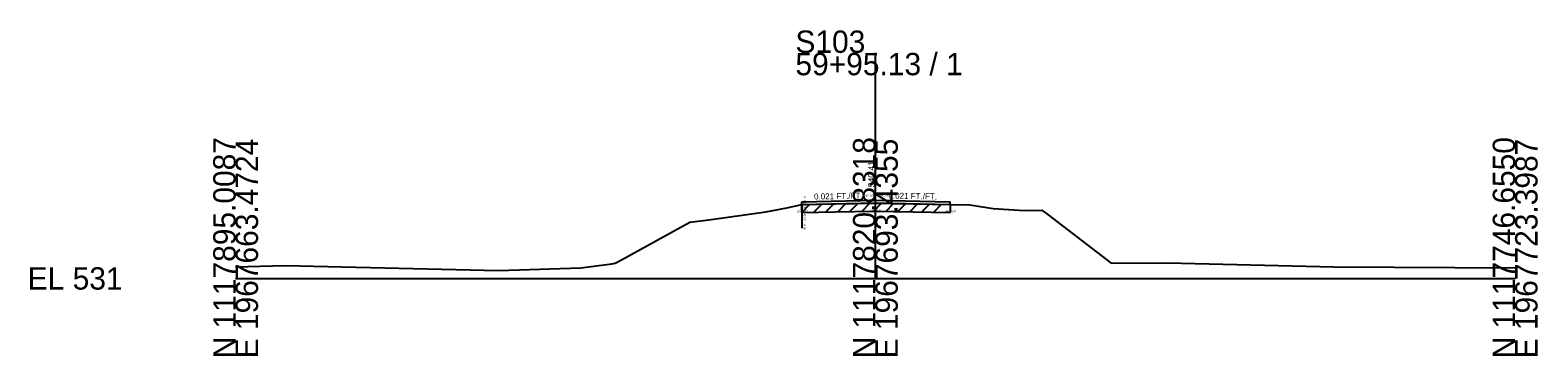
# Model space of a CAD drawing. Extents: x -26 to 163, y -10 to 24018.
# Drawn here: x -25.7 to 162.8, y 9490.3 to 9531.1 of the extents above; entities that cross this region are included whole.
import ezdxf

# ---------------------------------------------------------------- set-up
doc = ezdxf.new("R2010")
doc.units = 0
for name, color, linetype in [('RD_GPK_XS_Cell', 7, 'Continuous'), ('RD_XS_ExGround', 7, 'Continuous'), ('RD_XS_ExPaveRet', 7, 'Continuous'), ('RD_XS_Misc_Line', 7, 'Continuous'), ('RD_XS_PaveOvlay_CP', 7, 'Continuous'), ('RD_XS_TX_Elev_EX', 7, 'Continuous'), ('RD_XS_TX_ExEOP', 7, 'Continuous'), ('RD_XS_TX_Notes', 7, 'Continuous'), ('RD_XS_TX_Profile', 7, 'Continuous'), ('RD_XS_TX_Slope', 7, 'Continuous')]:
    doc.layers.add(name, color=color, linetype=linetype)

msp = doc.modelspace()

# ---------------------------------------------------------------- linework, layer by layer
at = {"layer": 'RD_GPK_XS_Cell'}
for p, q in [((80, 9500), (80, 9528.23)), ((0, 9500), (80, 9500)), ((80, 9500), (160, 9500))]:
    msp.add_line(p, q, dxfattribs=at)
at = {"layer": 'RD_XS_ExGround'}
msp.add_lwpolyline([(0, 9501.46), (6.2, 9501.6), (32.88, 9501), (43.17, 9501.32), (47.06, 9501.84), (47.47, 9501.9), (48.27, 9502.33), (56.8, 9507.05), (59.19, 9507.34), (66.3, 9508.34), (68.91, 9508.85), (70.79, 9509.27), (75.03, 9509.34), (79.82, 9509.41), (84.72, 9509.33), (89.35, 9509.26), (91.83, 9509.23), (94.74, 9508.75), (98.65, 9508.49), (100.8, 9508.53), (101.62, 9507.97), (109.48, 9501.91), (116.51, 9501.97), (137.33, 9501.45), (160, 9501.34)], dxfattribs=at)
at = {"layer": 'RD_XS_ExPaveRet'}
for p, q in [((70.79, 9508.27), (71.81, 9509.29)), ((70.79, 9508.27), (70.79, 9509.27)), ((70.79, 9508.27), (75.03, 9508.34)), ((72.29, 9508.29), (73.31, 9509.31)), ((73.79, 9508.32), (74.81, 9509.33)), ((75.03, 9508.34), (79.82, 9508.41)), ((75.29, 9508.34), (76.31, 9509.36)), ((76.79, 9508.36), (77.81, 9509.38)), ((78.29, 9508.39), (79.31, 9509.4)), ((79.79, 9508.41), (80.78, 9509.4)), ((79.82, 9508.41), (84.72, 9508.33)), ((81.29, 9508.39), (82.28, 9509.37)), ((82.79, 9508.36), (83.78, 9509.35)), ((84.29, 9508.34), (85.28, 9509.32)), ((84.72, 9508.33), (89.35, 9508.26)), ((85.79, 9508.32), (86.78, 9509.3)), ((87.29, 9508.29), (88.28, 9509.28)), ((89.35, 9509.26), (89.35, 9508.26))]:
    msp.add_line(p, q, dxfattribs=at)
at = {"layer": 'RD_XS_Misc_Line'}
msp.add_line((70.79, 9509.27), (70.79, 9506.27), dxfattribs=at)
at = {"layer": 'RD_XS_PaveOvlay_CP'}
for p, q in [((70.79, 9509.59), (80, 9509.78)), ((70.79, 9509.27), (70.79, 9509.59)), ((80, 9509.78), (89.35, 9509.59)), ((89.35, 9509.26), (89.35, 9509.59)), ((80, 9509.41), (70.79, 9509.22)), ((89.35, 9509.22), (80, 9509.41))]:
    msp.add_line(p, q, dxfattribs=at)

# ---------------------------------------------------------------- texts
at = {"layer": 'RD_GPK_XS_Cell'}
for s, p in [('S103', (70, 9528.23)), ('59+95.13 / 1', (70, 9525.43)), ('EL 531', (-26, 9498.6))]:
    msp.add_text(s, height=2.8, dxfattribs=at).set_placement(p)
for s, p in [('N 1117895.0087', (0, 9490)), ('E 1967663.4724', (2.8, 9490)), ('N 1117820.8318', (80, 9490)), ('E 1967693.4355', (82.8, 9490)), ('N 1117746.6550', (160, 9490)), ('E 1967723.3987', (162.8, 9490))]:
    msp.add_text(s, height=2.8, rotation=90, dxfattribs=at).set_placement(p)
at = {"layer": 'RD_XS_TX_Elev_EX'}
msp.add_text('540.41', height=0.8, rotation=90, dxfattribs=at).set_placement((79.9, 9511.41))
at = {"layer": 'RD_XS_TX_ExEOP'}
for s, p in [('EOP-L', (70.74, 9509.59)), ('EOP-R', (89.3, 9509.59))]:
    msp.add_text(s, height=0.1, rotation=270, dxfattribs=at).set_placement(p)
at = {"layer": 'RD_XS_TX_Notes'}
msp.add_text(' Min. Distance @CP = -0.05', height=0.25, rotation=270, dxfattribs=at).set_placement((71.04, 9510.36))
for s, p in [('Elev. @CL = 540.78', (78.48, 9510.28)), (' dE= 0.32', (70.08, 9508.27)), (' dE= 0.37', (79.29, 9508.41)), (' dE= 0.32', (88.63, 9508.26))]:
    msp.add_text(s, height=0.25, dxfattribs=at).set_placement(p)
at = {"layer": 'RD_XS_TX_Profile'}
msp.add_text('CL', height=0.25, dxfattribs=at).set_placement((79.77, 9509.78))
at = {"layer": 'RD_XS_TX_Slope'}
for rotation, p in [(1.1916, (72.34, 9509.87)), (358.8084, (81.63, 9510))]:
    msp.add_text('0.021 FT./FT.', height=0.75, rotation=rotation, dxfattribs=at).set_placement(p)

doc.saveas('drawing.dxf')
